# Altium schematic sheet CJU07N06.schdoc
size 127 x 101 mm
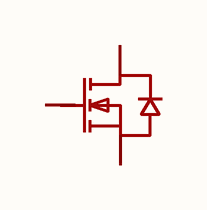
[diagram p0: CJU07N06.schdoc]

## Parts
Q?  cju07n06  [TO-252-2_L6.6-W6.1-P4.58-LS9.9-BR]  (value not drawn)

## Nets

Not connected (* = marked no-connect by the designer): Q? 1(G) 2(D) 3(S)

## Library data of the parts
Q? = cju07n06: 数量:1个N沟道;漏源电压(Vdss):60V;连续漏极电流(Id):7A;导通电阻(RDS(on)):88mΩ@4.5V;耗散功率(Pd):15W;阈值电压(Vgs(th)):2V;; Manufacturer: CJ(江苏长电/长晶); AddInBom: yes; ModelId: ce57f84d66384067af8a68020b6de06d; ModelName: TO-252-2L-3P_L6.6-W6.1-H2.3-LS10.1-P4.6; ModelTransform: 259.842,390.52442,0,90,0,0,-39.375,0,0; Number: 1个N沟道; Drain to Source Voltage: 60V; Current - Continuous Drain(Id): 7A; Pd - Power Dissipation: 15W; Gate Threshold Voltage (Vgs(th)): 2V; Gate Charge(Qg): 14nC@4.5V; Input Capacitance(Ciss): 308pF; Reverse Transfer Capacitance (Crss@Vds): 20.2pF; Type: N沟道; Output Capacitance(Coss): 22.6pF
